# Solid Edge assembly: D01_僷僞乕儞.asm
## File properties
Author: MOKUNO
Template: jis assembly.asm
Last saved by: edge
Revision: 8
Application: Solid Edge
文書内容のタイプ: 1
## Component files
D02_plate.par
D02_bolt.par
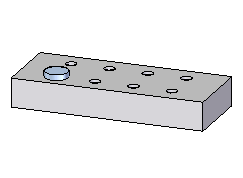
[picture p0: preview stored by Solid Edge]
